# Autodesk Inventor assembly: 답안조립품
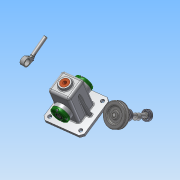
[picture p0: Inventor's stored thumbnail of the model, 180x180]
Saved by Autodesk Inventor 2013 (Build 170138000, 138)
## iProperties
Created: 2016-02
Part Number: 답안조립품
Document SubType Name: Assembly
Designer: Administrator
Author: Administrator
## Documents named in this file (16)
- C:\Users\Administrator\Desktop\460212V1004\답안조립품.iam
- C:\Users\Administrator\Desktop\460212V1004\본체.ipt
- C:\Users\Administrator\Desktop\460212V1004\V벨트풀리.ipt
- C:\Users\Administrator\Desktop\460212V1004\고정핀 1.2 x 10.ipt
- C:\Users\Administrator\Desktop\460212V1004\뒤커버.ipt
- C:\Users\Administrator\Desktop\460212V1004\링크.ipt
- C:\Users\Administrator\Desktop\460212V1004\멈춤나사 M3x8.ipt
- C:\Users\Administrator\Desktop\460212V1004\베어링 12 x 32 x 10.ipt
- C:\Users\Administrator\Desktop\460212V1004\볼트 M4 x 12.ipt
- C:\Users\Administrator\Desktop\460212V1004\부시.ipt
- C:\Users\Administrator\Desktop\460212V1004\슬라이드.ipt
- C:\Users\Administrator\Desktop\460212V1004\앞커버.ipt
- C:\Users\Administrator\Desktop\460212V1004\오일실 12 25 7.ipt
- C:\Users\Administrator\Desktop\460212V1004\키 4 x 4 x 10.ipt
- C:\Users\Administrator\Desktop\460212V1004\편심축.ipt
- C:\Users\Administrator\Desktop\460212V1004\핀 5 x 18.ipt
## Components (11 placed, 4 different names)
1. V벨트풀리:1
2. 고정핀 1.2 x 10:1
3. 핀 5 x 18:1
4. ISO 4762 M4 x 12:1
5. ISO 4762 M4 x 12:3
6. ISO 4762 M4 x 12:4
7. ISO 4762 M4 x 12:5
8. ISO 4762 M4 x 12:2
9. ISO 4762 M4 x 12:6
10. ISO 4762 M4 x 12:7
11. ISO 4762 M4 x 12:8
